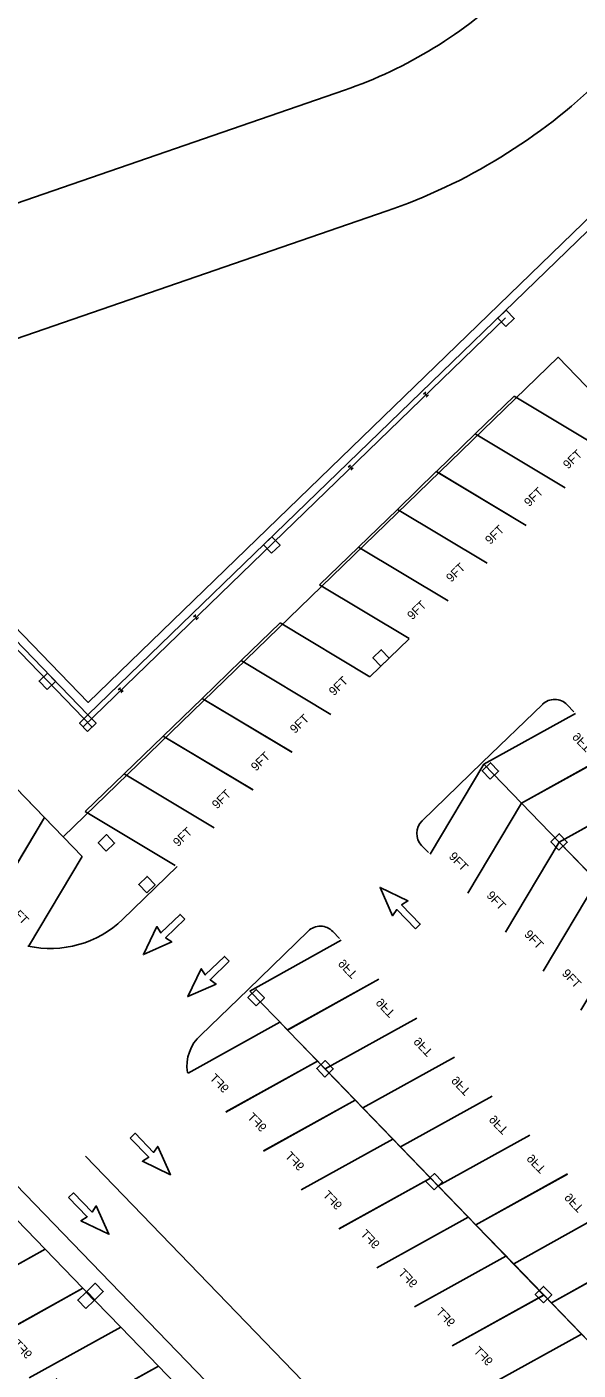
# Model space of a CAD drawing. Extents: x 468143 to 491361, y 1438528 to 1468730.
# Drawn here: x 490505.8 to 490600.6, y 1467620.4 to 1467851.1 of the extents above; entities that cross this region are included whole.
import ezdxf

# ---------------------------------------------------------------- set-up
doc = ezdxf.new("R2010")
doc.units = 0
doc.layers.add('Default', color=7, linetype='Continuous')
doc.layers.add('Xreference_dp', color=7, linetype='Continuous')

# ---------------------------------------------------------------- blocks, each defined once
blk = doc.blocks.new('STALL 9FT-75D')
at = {"layer": 'Default'}
for p, q in [((0, 0), (111.8, 0)), ((111.8, 0), (167.7, -208.6))]:
    blk.add_line(p, q, dxfattribs=at)
blk.add_lwpolyline([(55.9, -208.6), (0, 0)], dxfattribs=at)
blk.add_text('9FT', height=18, dxfattribs=at).set_placement((86.4, -185.9))
blk = doc.blocks.new('arrow-thru')
at = {"layer": 'Default'}
blk.add_lwpolyline([(14.99997, 0), (28.999942, 0), (28.999942, 54.99989), (43.999912, 51.999896), (21.999956, 111.999776), (0, 51.999896), (14.99997, 54.99989)], close=True, dxfattribs=at)
blk = doc.blocks.new('cable suppt')
at = {"layer": 'Default'}
for points in [[(-3.2, 4), (3.2, 4)], [(0, -4), (0, 4)], [(-3.2, -4), (3.2, -4)]]:
    blk.add_lwpolyline(points, dxfattribs=at)
blk = doc.blocks.new('cable suppt bay')
at = {"layer": 'Default'}
for p in [(227.999544, 0.999998), (443.999112, 0.999998)]:
    blk.add_blockref('cable suppt', p, dxfattribs=at)
blk = doc.blocks.new('Col 24x24')
at = {"layer": 'Default'}
blk.add_lwpolyline([(-11.999976, -11.999976), (-11.999976, 11.999976), (11.999976, 11.999976), (11.999976, -11.999976), (-11.999976, -11.999976)], dxfattribs=at)
blk.add_lwpolyline([(-11.999976, -11.999976), (11.999976, -11.999976), (11.999976, 11.999976), (-11.999976, 11.999976)], close=True, dxfattribs=at)

msp = doc.modelspace()

# ---------------------------------------------------------------- linework, layer by layer
at = {"layer": 'Xreference_dp'}
for p, q in [((490474.8, 1467810.68), (490560.43, 1467840.19)), ((490474.8, 1467810.68), (490560.43, 1467840.19)), ((490516.35, 1467732.9), (490628.56, 1467841.5)), ((490516.35, 1467732.9), (490628.56, 1467841.5)), ((490481.97, 1467789.88), (490567.59, 1467819.39)), ((490481.97, 1467789.88), (490567.59, 1467819.39)), ((490471.49, 1467779.24), (490516.35, 1467732.9)), ((490471.49, 1467779.24), (490516.35, 1467732.9)), ((490571.56, 1467745.99), (490564.8, 1467739.44)), ((490571.56, 1467745.99), (490564.8, 1467739.44)), ((490584.11, 1467724.71), (490594.45, 1467734.71)), ((490584.11, 1467724.71), (490594.45, 1467734.71)), ((490599.84, 1467733.45), (490598.69, 1467734.64)), ((490599.84, 1467733.45), (490598.69, 1467734.64)), ((490584.1, 1467724.71), (490573.76, 1467714.71)), ((490584.1, 1467724.71), (490573.76, 1467714.71)), ((490574.85, 1467709.27), (490573.69, 1467710.46)), ((490574.85, 1467709.27), (490573.69, 1467710.46)), ((490531.67, 1467706.84), (490522.31, 1467697.77)), ((490531.67, 1467706.84), (490522.31, 1467697.77)), ((490543.87, 1467685.76), (490554.21, 1467695.77)), ((490543.87, 1467685.76), (490554.21, 1467695.77)), ((490559.6, 1467694.51), (490558.45, 1467695.7)), ((490559.6, 1467694.51), (490558.45, 1467695.7)), ((490465.94, 1467691.51), (490575.37, 1467578.42)), ((490465.94, 1467691.51), (490575.37, 1467578.42)), ((490515.94, 1467657.1), (490583.99, 1467586.77)), ((490515.94, 1467657.1), (490583.99, 1467586.77))]:
    msp.add_line(p, q, dxfattribs=at)
msp.add_lwpolyline([(490342.06, 1467246.02), (490137.16, 1467457.76), (490471.58, 1467781.33), (490516.38, 1467735.04), (490628.6, 1467843.61), (490790.28, 1467676.55), (490385, 1467284.32)], close=True, dxfattribs=at)
msp.add_lwpolyline([(490342.06, 1467246.02), (490137.16, 1467457.76), (490471.58, 1467781.33), (490516.38, 1467735.04), (490628.6, 1467843.61), (490790.28, 1467676.55), (490385, 1467284.32)], close=True, dxfattribs=at)
for points in [[(490385.72, 1467679.47), (490454.03, 1467745.57), (490462.92, 1467736.38), (490476.11, 1467749.14), (490512.08, 1467711.97), (490597.15, 1467794.31), (490608.23, 1467782.86), (490646.1, 1467819.51)], [(490385.72, 1467679.47), (490454.03, 1467745.57), (490462.92, 1467736.38), (490476.11, 1467749.14), (490512.08, 1467711.97), (490597.15, 1467794.31), (490608.23, 1467782.86), (490646.1, 1467819.51)], [(490588.12, 1467801.08), (490515.55, 1467730.85)], [(490588.12, 1467801.08), (490515.55, 1467730.85)], [(490487.87, 1467761), (490517.08, 1467730.82)], [(490487.87, 1467761), (490517.08, 1467730.82)], [(490535.75, 1467677.91), (490543.87, 1467685.76)], [(490535.75, 1467677.91), (490543.87, 1467685.76)], [(490533.57, 1467671.39), (490533.46, 1467671.51)], [(490533.57, 1467671.39), (490533.46, 1467671.51)]]:
    msp.add_lwpolyline(points, dxfattribs=at)
for centre, radius, start, end in [((490535.01, 1467913.93), 78, 289.016, 314.0456), ((490535.01, 1467913.93), 78, 289.016, 314.0456), ((490535.01, 1467913.93), 100, 289.016, 314.0456), ((490535.01, 1467913.93), 100, 289.016, 314.0456), ((490596.53, 1467732.56), 3, 44.0688, 134.0688), ((490596.53, 1467732.56), 3, 44.0688, 134.0688), ((490575.85, 1467712.55), 3, 134.0688, 224.0688), ((490575.85, 1467712.55), 3, 134.0688, 224.0688), ((490509.9, 1467710.7), 17.92, 257.5716, 313.8057), ((490509.9, 1467710.7), 17.92, 257.5716, 313.8057), ((490556.29, 1467693.61), 3, 44.0688, 134.0688), ((490556.29, 1467693.61), 3, 44.0688, 134.0688), ((490540.36, 1467672.64), 7, 131.2592, 189.2944), ((490540.36, 1467672.64), 7, 131.2592, 189.2944)]:
    msp.add_arc(centre, radius, start, end, dxfattribs=at)

# ---------------------------------------------------------------- block references
for name, p, xscale, yscale, rotation in [('Col 24x24', (490588.18, 1467801.02), 0.0833307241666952, 0.0833307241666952, 44.062944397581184), ('Col 24x24', (490588.18, 1467801.02), 0.0833307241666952, 0.0833307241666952, 44.062944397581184), ('STALL 9FT-75D', (490582.91, 1467781.16), 0.08333072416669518, 0.0833307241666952, 44.051197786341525), ('STALL 9FT-75D', (490582.91, 1467781.16), 0.08333072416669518, 0.0833307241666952, 44.051197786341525), ('cable suppt bay', (490547.9, 1467762.12), 0.08333072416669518, 0.0833307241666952, 44.06293670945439), ('cable suppt bay', (490547.9, 1467762.12), 0.08333072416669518, 0.0833307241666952, 44.06293670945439), ('STALL 9FT-75D', (490576.22, 1467774.68), 0.08333072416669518, 0.0833307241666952, 44.051197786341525), ('STALL 9FT-75D', (490576.22, 1467774.68), 0.08333072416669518, 0.0833307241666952, 44.051197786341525), ('STALL 9FT-75D', (490569.52, 1467768.2), 0.08333072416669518, 0.0833307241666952, 44.051197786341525), ('STALL 9FT-75D', (490569.52, 1467768.2), 0.08333072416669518, 0.0833307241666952, 44.051197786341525), ('STALL 9FT-75D', (490562.82, 1467761.72), 0.08333072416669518, 0.0833307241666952, 44.051197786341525), ('STALL 9FT-75D', (490562.82, 1467761.72), 0.08333072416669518, 0.0833307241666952, 44.051197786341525), ('Col 24x24', (490547.94, 1467762.08), 0.0833307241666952, 0.0833307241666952, 44.062944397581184), ('Col 24x24', (490547.94, 1467762.08), 0.0833307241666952, 0.0833307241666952, 44.062944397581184), ('STALL 9FT-75D', (490556.13, 1467755.25), 0.08333072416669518, 0.0833307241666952, 44.051197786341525), ('STALL 9FT-75D', (490556.13, 1467755.25), 0.08333072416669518, 0.0833307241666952, 44.051197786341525), ('STALL 9FT-75D', (490542.67, 1467742.22), 0.08333072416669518, 0.0833307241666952, 44.051197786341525), ('STALL 9FT-75D', (490542.67, 1467742.22), 0.08333072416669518, 0.0833307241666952, 44.051197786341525), ('cable suppt bay', (490508.38, 1467723.87), 0.08333072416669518, 0.0833307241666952, 44.06293670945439), ('cable suppt bay', (490508.38, 1467723.87), 0.08333072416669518, 0.0833307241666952, 44.06293670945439), ('STALL 9FT-75D', (490535.98, 1467735.74), 0.08333072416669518, 0.0833307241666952, 44.051197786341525), ('STALL 9FT-75D', (490535.98, 1467735.74), 0.08333072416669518, 0.0833307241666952, 44.051197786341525), ('Col 24x24', (490566.72, 1467742.68), 0.0833307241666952, 0.0833307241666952, 44.062944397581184), ('Col 24x24', (490566.72, 1467742.68), 0.0833307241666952, 0.0833307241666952, 44.062944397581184), ('Col 24x24', (490509.37, 1467738.67), 0.0833307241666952, 0.0833307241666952, 44.062944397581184), ('Col 24x24', (490509.37, 1467738.67), 0.0833307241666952, 0.0833307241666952, 44.062944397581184), ('STALL 9FT-75D', (490529.28, 1467729.26), 0.08333072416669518, 0.0833307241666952, 44.051197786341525), ('STALL 9FT-75D', (490529.28, 1467729.26), 0.08333072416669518, 0.0833307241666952, 44.051197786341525), ('STALL 9FT-75D', (490584.39, 1467724.42), 0.0833307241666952, -0.08333072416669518, -45.93119382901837), ('STALL 9FT-75D', (490584.39, 1467724.42), 0.0833307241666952, -0.08333072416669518, -45.93119382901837), ('Col 24x24', (490516.32, 1467731.48), 0.0833307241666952, 0.0833307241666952, 44.062944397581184), ('Col 24x24', (490516.32, 1467731.48), 0.0833307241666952, 0.0833307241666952, 44.062944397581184), ('STALL 9FT-75D', (490522.58, 1467722.78), 0.08333072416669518, 0.0833307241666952, 44.051197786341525), ('STALL 9FT-75D', (490522.58, 1467722.78), 0.08333072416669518, 0.0833307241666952, 44.051197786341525), ('STALL 9FT-75D', (490590.87, 1467717.73), 0.0833307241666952, -0.08333072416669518, -45.93119382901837), ('STALL 9FT-75D', (490590.87, 1467717.73), 0.0833307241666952, -0.08333072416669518, -45.93119382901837), ('STALL 9FT-75D', (490515.89, 1467716.3), 0.08333072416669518, 0.0833307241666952, 44.051197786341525), ('STALL 9FT-75D', (490515.89, 1467716.3), 0.08333072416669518, 0.0833307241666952, 44.051197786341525), ('STALL 9FT-75D', (490584.38, 1467724.43), 0.08333072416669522, 0.08333072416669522, -45.93119382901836), ('STALL 9FT-75D', (490584.38, 1467724.43), 0.08333072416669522, 0.08333072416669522, -45.93119382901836), ('Col 24x24', (490585.49, 1467723.28), 0.0833307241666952, 0.0833307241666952, 44.062944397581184), ('Col 24x24', (490585.49, 1467723.28), 0.0833307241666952, 0.0833307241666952, 44.062944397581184), ('STALL 9FT-75D', (490502.41, 1467721.97), 0.08333072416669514, 0.08333072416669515, -45.942932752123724), ('STALL 9FT-75D', (490502.41, 1467721.97), 0.08333072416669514, 0.08333072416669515, -45.942932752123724), ('STALL 9FT-75D', (490597.35, 1467711.03), 0.0833307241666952, -0.08333072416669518, -45.93119382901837), ('STALL 9FT-75D', (490597.35, 1467711.03), 0.0833307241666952, -0.08333072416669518, -45.93119382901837), ('STALL 9FT-75D', (490590.86, 1467717.73), 0.08333072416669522, 0.08333072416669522, -45.93119382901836), ('STALL 9FT-75D', (490590.86, 1467717.73), 0.08333072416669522, 0.08333072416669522, -45.93119382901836), ('STALL 9FT-75D', (490508.89, 1467715.27), 0.08333072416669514, 0.08333072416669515, -45.942932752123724), ('STALL 9FT-75D', (490508.89, 1467715.27), 0.08333072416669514, 0.08333072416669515, -45.942932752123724), ('Col 24x24', (490597.31, 1467711.06), 0.0833307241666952, 0.0833307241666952, 44.062944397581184), ('Col 24x24', (490597.31, 1467711.06), 0.0833307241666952, 0.0833307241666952, 44.062944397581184), ('Col 24x24', (490519.52, 1467710.92), 0.0833307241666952, 0.0833307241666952, 44.062944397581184), ('Col 24x24', (490519.52, 1467710.92), 0.0833307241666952, 0.0833307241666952, 44.062944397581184), ('STALL 9FT-75D', (490597.34, 1467711.04), 0.08333072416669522, 0.08333072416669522, -45.93119382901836), ('STALL 9FT-75D', (490597.34, 1467711.04), 0.08333072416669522, 0.08333072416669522, -45.93119382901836), ('Col 24x24', (490526.48, 1467703.74), 0.0833307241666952, 0.0833307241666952, 44.062944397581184), ('Col 24x24', (490526.48, 1467703.74), 0.0833307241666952, 0.0833307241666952, 44.062944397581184), ('arrow-thru', (490571.71, 1467695.3), 0.0833307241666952, 0.08333072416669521, 44.06880617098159), ('arrow-thru', (490571.71, 1467695.3), 0.0833307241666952, 0.08333072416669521, 44.06880617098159), ('STALL 9FT-75D', (490603.82, 1467704.34), 0.08333072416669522, 0.08333072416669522, -45.93119382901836), ('STALL 9FT-75D', (490603.82, 1467704.34), 0.08333072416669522, 0.08333072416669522, -45.93119382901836), ('arrow-thru', (490533.85, 1467696.91), 0.0833307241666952, 0.08333072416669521, 134.05706724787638), ('arrow-thru', (490533.85, 1467696.91), 0.0833307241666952, 0.08333072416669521, 134.05706724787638), ('STALL 9FT-75D', (490544.15, 1467685.48), 0.0833307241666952, -0.08333072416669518, -45.93119382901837), ('STALL 9FT-75D', (490544.15, 1467685.48), 0.0833307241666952, -0.08333072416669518, -45.93119382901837), ('STALL 9FT-75D', (490610.3, 1467697.65), 0.08333072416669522, 0.08333072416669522, -45.93119382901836), ('STALL 9FT-75D', (490610.3, 1467697.65), 0.08333072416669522, 0.08333072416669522, -45.93119382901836), ('arrow-thru', (490541.49, 1467689.69), 0.0833307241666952, 0.08333072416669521, 134.05706724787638), ('arrow-thru', (490541.49, 1467689.69), 0.0833307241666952, 0.08333072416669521, 134.05706724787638), ('STALL 9FT-75D', (490550.63, 1467678.78), 0.0833307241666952, -0.08333072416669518, -45.93119382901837), ('STALL 9FT-75D', (490550.63, 1467678.78), 0.0833307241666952, -0.08333072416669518, -45.93119382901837), ('Col 24x24', (490545.25, 1467684.33), 0.0833307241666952, 0.0833307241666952, 44.062944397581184), ('Col 24x24', (490545.25, 1467684.33), 0.0833307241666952, 0.0833307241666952, 44.062944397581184), ('STALL 9FT-75D', (490555.78, 1467673.44), 0.08333072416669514, -0.08333072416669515, 134.0570672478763), ('STALL 9FT-75D', (490555.78, 1467673.44), 0.08333072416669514, -0.08333072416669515, 134.0570672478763), ('STALL 9FT-75D', (490557.11, 1467672.09), 0.0833307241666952, -0.08333072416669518, -45.93119382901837), ('STALL 9FT-75D', (490557.11, 1467672.09), 0.0833307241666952, -0.08333072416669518, -45.93119382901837), ('STALL 9FT-75D', (490562.26, 1467666.74), 0.08333072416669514, -0.08333072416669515, 134.0570672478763), ('STALL 9FT-75D', (490562.26, 1467666.74), 0.08333072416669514, -0.08333072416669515, 134.0570672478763), ('STALL 9FT-75D', (490563.59, 1467665.39), 0.0833307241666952, -0.08333072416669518, -45.93119382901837), ('STALL 9FT-75D', (490563.59, 1467665.39), 0.0833307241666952, -0.08333072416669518, -45.93119382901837), ('Col 24x24', (490557.08, 1467672.12), 0.0833307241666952, 0.0833307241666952, 44.062944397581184), ('Col 24x24', (490557.08, 1467672.12), 0.0833307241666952, 0.0833307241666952, 44.062944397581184), ('STALL 9FT-75D', (490568.74, 1467660.05), 0.08333072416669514, -0.08333072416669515, 134.0570672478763), ('STALL 9FT-75D', (490568.74, 1467660.05), 0.08333072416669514, -0.08333072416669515, 134.0570672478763), ('STALL 9FT-75D', (490570.07, 1467658.7), 0.0833307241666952, -0.08333072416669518, -45.93119382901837), ('STALL 9FT-75D', (490570.07, 1467658.7), 0.0833307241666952, -0.08333072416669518, -45.93119382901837), ('STALL 9FT-75D', (490576.55, 1467652), 0.0833307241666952, -0.08333072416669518, -45.93119382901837), ('STALL 9FT-75D', (490576.55, 1467652), 0.0833307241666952, -0.08333072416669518, -45.93119382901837), ('arrow-thru', (490522.7, 1467659.36), 0.08333072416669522, -0.08333072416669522, 44.057067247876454), ('arrow-thru', (490522.7, 1467659.36), 0.08333072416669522, -0.08333072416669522, 44.057067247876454), ('STALL 9FT-75D', (490575.22, 1467653.35), 0.08333072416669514, -0.08333072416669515, 134.0570672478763), ('STALL 9FT-75D', (490575.22, 1467653.35), 0.08333072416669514, -0.08333072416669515, 134.0570672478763), ('STALL 9FT-75D', (490583.03, 1467645.31), 0.0833307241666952, -0.08333072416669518, -45.93119382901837), ('STALL 9FT-75D', (490583.03, 1467645.31), 0.0833307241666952, -0.08333072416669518, -45.93119382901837), ('STALL 9FT-75D', (490581.7, 1467646.66), 0.08333072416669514, -0.08333072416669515, 134.0570672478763), ('STALL 9FT-75D', (490581.7, 1467646.66), 0.08333072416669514, -0.08333072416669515, 134.0570672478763), ('Col 24x24', (490575.85, 1467652.72), 0.0833307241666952, 0.0833307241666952, 44.062944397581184), ('Col 24x24', (490575.85, 1467652.72), 0.0833307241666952, 0.0833307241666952, 44.062944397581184), ('STALL 9FT-75D', (490509.01, 1467641.15), 0.08333072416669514, -0.08333072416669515, 134.0570672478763), ('STALL 9FT-75D', (490509.01, 1467641.15), 0.08333072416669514, -0.08333072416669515, 134.0570672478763), ('arrow-thru', (490512.13, 1467649.13), 0.08333072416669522, -0.08333072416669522, 44.057067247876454), ('arrow-thru', (490512.13, 1467649.13), 0.08333072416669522, -0.08333072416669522, 44.057067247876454), ('STALL 9FT-75D', (490589.51, 1467638.62), 0.0833307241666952, -0.08333072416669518, -45.93119382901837), ('STALL 9FT-75D', (490589.51, 1467638.62), 0.0833307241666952, -0.08333072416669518, -45.93119382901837), ('STALL 9FT-75D', (490588.18, 1467639.96), 0.08333072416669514, -0.08333072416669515, 134.0570672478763), ('STALL 9FT-75D', (490588.18, 1467639.96), 0.08333072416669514, -0.08333072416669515, 134.0570672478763), ('STALL 9FT-75D', (490515.49, 1467634.46), 0.08333072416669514, -0.08333072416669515, 134.0570672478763), ('STALL 9FT-75D', (490515.49, 1467634.46), 0.08333072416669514, -0.08333072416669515, 134.0570672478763), ('STALL 9FT-75D', (490594.66, 1467633.26), 0.08333072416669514, -0.08333072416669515, 134.0570672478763), ('STALL 9FT-75D', (490594.66, 1467633.26), 0.08333072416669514, -0.08333072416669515, 134.0570672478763), ('STALL 9FT-75D', (490595.99, 1467631.92), 0.0833307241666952, -0.08333072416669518, -45.93119382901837), ('STALL 9FT-75D', (490595.99, 1467631.92), 0.0833307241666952, -0.08333072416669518, -45.93119382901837), ('STALL 9FT-75D', (490521.97, 1467627.76), 0.08333072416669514, -0.08333072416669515, 134.0570672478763), ('STALL 9FT-75D', (490521.97, 1467627.76), 0.08333072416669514, -0.08333072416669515, 134.0570672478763), ('STALL 9FT-75D', (490601.14, 1467626.57), 0.08333072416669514, -0.08333072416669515, 134.0570672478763), ('STALL 9FT-75D', (490601.14, 1467626.57), 0.08333072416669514, -0.08333072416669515, 134.0570672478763), ('Col 24x24', (490517.55, 1467633.87), 0.0833307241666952, 0.0833307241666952, 44.062944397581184), ('Col 24x24', (490517.55, 1467633.87), 0.0833307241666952, 0.0833307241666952, 44.062944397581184), ('Col 24x24', (490594.63, 1467633.32), 0.0833307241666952, 0.0833307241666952, 44.062944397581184), ('Col 24x24', (490594.63, 1467633.32), 0.0833307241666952, 0.0833307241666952, 44.062944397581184), ('Col 24x24', (490516, 1467632.36), 0.0833307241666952, 0.0833307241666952, 44.062944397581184), ('Col 24x24', (490516, 1467632.36), 0.0833307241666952, 0.0833307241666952, 44.062944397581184), ('STALL 9FT-75D', (490528.45, 1467621.07), 0.08333072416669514, -0.08333072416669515, 134.0570672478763), ('STALL 9FT-75D', (490528.45, 1467621.07), 0.08333072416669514, -0.08333072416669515, 134.0570672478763), ('STALL 9FT-75D', (490607.62, 1467619.87), 0.08333072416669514, -0.08333072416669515, 134.0570672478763), ('STALL 9FT-75D', (490607.62, 1467619.87), 0.08333072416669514, -0.08333072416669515, 134.0570672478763), ('STALL 9FT-75D', (490534.93, 1467614.37), 0.08333072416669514, -0.08333072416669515, 134.0570672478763), ('STALL 9FT-75D', (490534.93, 1467614.37), 0.08333072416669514, -0.08333072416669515, 134.0570672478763), ('STALL 9FT-75D', (490614.1, 1467613.18), 0.08333072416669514, -0.08333072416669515, 134.0570672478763), ('STALL 9FT-75D', (490614.1, 1467613.18), 0.08333072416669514, -0.08333072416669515, 134.0570672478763)]:
    msp.add_blockref(name, p, dxfattribs=dict(at, xscale=xscale, yscale=yscale, rotation=rotation))

doc.saveas('drawing.dxf')
